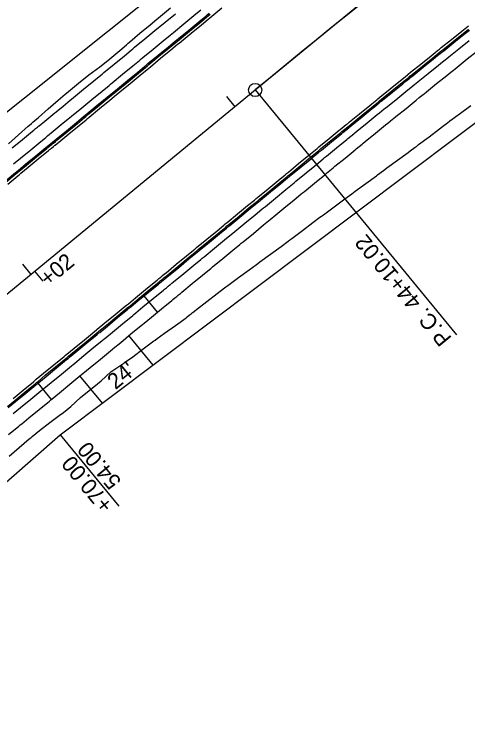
# Model space of a CAD drawing. Extents: x 1147550 to 1149124, y 2017436 to 2018779.
# Drawn here: x 1147734.3 to 1147906, y 2017436.4 to 2017707.7 of the extents above; entities that cross this region are included whole.
import ezdxf

# ---------------------------------------------------------------- set-up
doc = ezdxf.new("R2010")
doc.units = 0
for name, color, linetype in [('S_EDGE_CONCRETE', 7, 'Continuous'), ('S_ELECTRIC_UTILITIES', 7, 'Continuous'), ('S_HEADWALL', 7, 'Continuous'), ('S_MAILBOX', 7, 'Continuous'), ('S_RDW_PT_SYM', 7, 'Continuous'), ('S_SECONDARY_CTL', 7, 'Continuous'), ('S_TELEPHONE_UTILITIES', 7, 'Continuous')]:
    doc.layers.add(name, color=color, linetype=linetype)

msp = doc.modelspace()

# ---------------------------------------------------------------- linework, layer by layer
at = {"layer": 'S_EDGE_CONCRETE'}
for p, q in [((1147825.51, 2017679.08), (1148011.14, 2017831.73)), ((1147586.06, 2017482.16), (1147825.51, 2017679.08))]:
    msp.add_line(p, q, dxfattribs=at)
for points in [[(1147814.6, 2017676.58), (1147817.77, 2017672.72)], [(1147737.36, 2017613.06), (1147740.54, 2017609.2)]]:
    msp.add_lwpolyline(points, dxfattribs=at)
msp.add_circle((1147825.51, 2017679.08), 2.5, dxfattribs=at)
msp.add_arc((1151464.82, 2013253.76), 5729.58, 124.62946, 129.43332, dxfattribs=at)
at = {"layer": 'S_ELECTRIC_UTILITIES'}
msp.add_lwpolyline([(1147751.67, 2017548.43), (1147773.9, 2017521.4)], dxfattribs=at)
at = {"layer": 'S_HEADWALL'}
for p, q in [((1147745.26, 2017606.61), (1147742.08, 2017610.47)), ((1147788.52, 2017594.93), (1147783.44, 2017601.11)), ((1147786.87, 2017574.91), (1147777.71, 2017586.04)), ((1147767.67, 2017560.47), (1147759.17, 2017570.79)), ((1147748.36, 2017561.9), (1147743.28, 2017568.08))]:
    msp.add_line(p, q, dxfattribs=at)
at = {"layer": 'S_MAILBOX'}
for points in [[(1147550.1, 2017525.89), (1147894.72, 2017801.4), (1147903.55, 2017831.14), (1148035.64, 2017933.4), (1148261.5, 2018084.85), (1148285.74, 2018084.65), (1148479.1, 2018223.18), (1148835.76, 2018573.62)], [(1147623.68, 2017436.42), (1147751.67, 2017548.43), (1147958.55, 2017704.02), (1148020.45, 2017753.36), (1148124.6, 2017828.73), (1148174.25, 2017853.51), (1148282.74, 2017941.53), (1148421.63, 2018031.39), (1148612.18, 2018197.22), (1148639.91, 2018214.06), (1148753.45, 2018306.48), (1148799.03, 2018350.69)]]:
    msp.add_lwpolyline(points, dxfattribs=at)
at = {"layer": 'S_RDW_PT_SYM'}
msp.add_lwpolyline([(1147825.51, 2017679.08), (1147901.73, 2017586.39)], dxfattribs=at)
at = {"layer": 'S_SECONDARY_CTL'}
for points in [[(1147732.17, 2017658.73), (1147735.88, 2017662.1), (1147739.61, 2017665.43), (1147740.04, 2017665.8), (1147740.76, 2017666.41), (1147741.44, 2017666.99), (1147742, 2017667.46), (1147742.1, 2017667.55), (1147742.83, 2017668.16), (1147743.42, 2017668.66), (1147747.18, 2017671.97), (1147750.95, 2017675.26), (1147753.57, 2017677.45), (1147754.06, 2017677.87), (1147754.78, 2017678.47), (1147758.61, 2017681.68), (1147762.55, 2017684.76), (1147765.28, 2017686.81), (1147765.8, 2017687.2), (1147766.55, 2017687.77), (1147770.47, 2017690.88), (1147774.31, 2017694.08), (1147776.82, 2017696.23), (1147777.46, 2017696.78), (1147778.11, 2017697.34), (1147781.89, 2017700.6), (1147785.74, 2017703.79), (1147788.32, 2017705.92), (1147788.9, 2017706.4), (1147789.6, 2017706.98), (1147793.45, 2017710.16)], [(1147732.37, 2017540.41), (1147736.17, 2017543.66), (1147739.97, 2017546.91), (1147740.53, 2017547.38), (1147741.05, 2017547.83), (1147743.83, 2017550.09), (1147747.82, 2017553.12), (1147751.8, 2017556.14), (1147752.39, 2017556.58), (1147752.93, 2017556.99), (1147755.72, 2017559.25), (1147759.42, 2017562.63), (1147763.3, 2017565.77), (1147763.87, 2017566.23), (1147764.4, 2017566.66), (1147767.19, 2017568.91), (1147770.91, 2017572.27), (1147775.01, 2017575.16), (1147775.74, 2017575.65), (1147776.04, 2017575.87), (1147779.15, 2017577.99), (1147783.07, 2017581.09), (1147787.13, 2017584.03), (1147787.6, 2017584.36), (1147788.37, 2017584.92), (1147791.2, 2017586.96), (1147795.28, 2017589.87), (1147799.32, 2017592.83), (1147799.77, 2017593.18), (1147800.51, 2017593.76), (1147801.22, 2017594.3), (1147801.8, 2017594.75), (1147801.9, 2017594.83), (1147802.65, 2017595.41), (1147803.27, 2017595.89), (1147807.22, 2017598.96), (1147811.17, 2017602.03), (1147813.87, 2017604.12), (1147814.39, 2017604.52), (1147815.12, 2017605.09), (1147819.15, 2017608.07), (1147823.2, 2017611.01), (1147825.97, 2017613.02), (1147826.5, 2017613.4), (1147827.26, 2017613.95), (1147831.31, 2017616.89), (1147835.37, 2017619.83), (1147838.01, 2017621.82), (1147838.69, 2017622.34), (1147839.36, 2017622.85), (1147843.37, 2017625.85), (1147847.38, 2017628.85), (1147850.05, 2017630.85), (1147850.67, 2017631.3), (1147851.39, 2017631.84), (1147855.4, 2017634.83), (1147859.43, 2017637.8), (1147859.45, 2017637.81), (1147862.09, 2017639.77), (1147862.69, 2017640.21), (1147863.42, 2017640.75), (1147867.42, 2017643.69), (1147871.42, 2017646.62), (1147871.83, 2017646.92), (1147874.13, 2017648.62), (1147874.59, 2017648.95), (1147875.42, 2017649.56), (1147879.42, 2017652.48), (1147883.41, 2017655.42), (1147884.22, 2017656.02), (1147886.13, 2017657.43), (1147886.54, 2017657.74), (1147887.39, 2017658.39), (1147891.33, 2017661.39), (1147895.27, 2017664.38), (1147896.46, 2017665.28), (1147897.97, 2017666.43), (1147898.34, 2017666.7), (1147899.22, 2017667.37), (1147903.21, 2017670.32), (1147907.2, 2017673.25)]]:
    msp.add_lwpolyline(points, dxfattribs=at)
at = {"layer": 'S_TELEPHONE_UTILITIES'}
for points in [[(1147731.8, 2017643.44), (1147735.66, 2017646.62), (1147736.1, 2017646.98), (1147736.83, 2017647.58), (1147739.52, 2017649.79), (1147743.38, 2017652.97), (1147747.24, 2017656.14), (1147747.68, 2017656.51), (1147748.41, 2017657.11), (1147749.1, 2017657.67), (1147749.67, 2017658.14), (1147749.77, 2017658.22), (1147750.5, 2017658.82), (1147751.11, 2017659.32), (1147754.97, 2017662.5), (1147758.83, 2017665.67), (1147761.47, 2017667.84), (1147761.97, 2017668.26), (1147762.69, 2017668.85), (1147766.55, 2017672.02), (1147770.42, 2017675.2), (1147773.05, 2017677.37), (1147773.55, 2017677.78), (1147774.28, 2017678.38), (1147778.14, 2017681.55), (1147782, 2017684.73), (1147784.55, 2017686.82), (1147785.21, 2017687.36), (1147785.86, 2017687.9), (1147789.72, 2017691.08), (1147793.59, 2017694.26), (1147796.16, 2017696.38), (1147796.75, 2017696.86), (1147797.45, 2017697.43), (1147801.31, 2017700.61), (1147805.17, 2017703.78), (1147805.18, 2017703.79), (1147807.76, 2017705.91), (1147808.34, 2017706.39), (1147809.06, 2017706.98), (1147812.94, 2017710.16)], [(1147730.84, 2017644.6), (1147734.71, 2017647.78), (1147735.15, 2017648.14), (1147735.88, 2017648.74), (1147738.57, 2017650.95), (1147742.43, 2017654.13), (1147746.29, 2017657.3), (1147746.73, 2017657.67), (1147747.46, 2017658.27), (1147748.15, 2017658.83), (1147748.72, 2017659.3), (1147748.82, 2017659.38), (1147749.55, 2017659.98), (1147750.15, 2017660.48), (1147754.02, 2017663.66), (1147757.88, 2017666.83), (1147760.52, 2017669), (1147761.02, 2017669.41), (1147761.74, 2017670.01), (1147765.6, 2017673.18), (1147769.46, 2017676.36), (1147772.1, 2017678.53), (1147772.6, 2017678.94), (1147773.32, 2017679.53), (1147777.19, 2017682.71), (1147781.05, 2017685.89), (1147783.6, 2017687.98), (1147784.25, 2017688.52), (1147784.91, 2017689.06), (1147788.77, 2017692.24), (1147792.63, 2017695.41), (1147795.21, 2017697.53), (1147795.8, 2017698.02), (1147796.5, 2017698.59), (1147800.36, 2017701.77), (1147804.22, 2017704.94), (1147804.23, 2017704.95), (1147806.81, 2017707.07), (1147807.39, 2017707.55), (1147808.1, 2017708.13)], [(1147731.16, 2017644.21), (1147735.02, 2017647.39), (1147735.47, 2017647.76), (1147736.2, 2017648.36), (1147738.89, 2017650.57), (1147742.75, 2017653.74), (1147746.61, 2017656.92), (1147747.05, 2017657.28), (1147747.78, 2017657.88), (1147748.47, 2017658.45), (1147749.04, 2017658.91), (1147749.14, 2017659), (1147749.87, 2017659.6), (1147750.47, 2017660.09), (1147754.33, 2017663.27), (1147758.19, 2017666.44), (1147760.84, 2017668.62), (1147761.34, 2017669.03), (1147762.06, 2017669.62), (1147765.92, 2017672.8), (1147769.78, 2017675.97), (1147772.41, 2017678.14), (1147772.92, 2017678.55), (1147773.64, 2017679.15), (1147777.5, 2017682.32), (1147781.37, 2017685.5), (1147783.92, 2017687.6), (1147784.57, 2017688.14), (1147785.23, 2017688.68), (1147789.09, 2017691.85), (1147792.95, 2017695.03), (1147795.53, 2017697.15), (1147796.12, 2017697.63), (1147796.81, 2017698.2), (1147800.67, 2017701.38), (1147804.54, 2017704.56), (1147804.55, 2017704.57), (1147807.13, 2017706.68), (1147807.71, 2017707.16), (1147808.42, 2017707.75)], [(1147733.49, 2017657.13), (1147737.35, 2017660.31), (1147741.21, 2017663.48), (1147741.65, 2017663.84), (1147742.38, 2017664.44), (1147743.07, 2017665.01), (1147743.64, 2017665.48), (1147743.74, 2017665.56), (1147744.47, 2017666.16), (1147745.07, 2017666.66), (1147748.93, 2017669.83), (1147752.8, 2017673.01), (1147755.44, 2017675.18), (1147755.94, 2017675.59), (1147756.66, 2017676.19), (1147760.52, 2017679.36), (1147764.38, 2017682.54), (1147767.02, 2017684.7), (1147767.52, 2017685.12), (1147768.24, 2017685.71), (1147772.1, 2017688.89), (1147775.97, 2017692.07), (1147778.52, 2017694.16), (1147779.17, 2017694.7), (1147779.83, 2017695.24), (1147783.69, 2017698.42), (1147787.55, 2017701.59), (1147790.13, 2017703.71), (1147790.72, 2017704.2), (1147791.41, 2017704.77), (1147795.28, 2017707.94)], [(1147733.98, 2017651.06), (1147736.66, 2017653.27), (1147740.52, 2017656.44), (1147744.39, 2017659.62), (1147744.83, 2017659.98), (1147745.56, 2017660.58), (1147746.25, 2017661.15), (1147746.81, 2017661.62), (1147746.92, 2017661.7), (1147747.64, 2017662.3), (1147748.25, 2017662.8), (1147752.11, 2017665.97), (1147755.97, 2017669.15), (1147758.61, 2017671.32), (1147759.11, 2017671.73), (1147759.83, 2017672.32), (1147763.7, 2017675.5), (1147767.56, 2017678.68), (1147770.19, 2017680.84), (1147770.69, 2017681.25), (1147771.42, 2017681.85), (1147775.28, 2017685.03), (1147779.14, 2017688.2), (1147781.69, 2017690.3), (1147782.35, 2017690.84), (1147783, 2017691.38), (1147786.87, 2017694.56), (1147790.73, 2017697.73), (1147793.31, 2017699.85), (1147793.89, 2017700.34), (1147794.59, 2017700.91), (1147798.45, 2017704.08), (1147802.31, 2017707.26), (1147802.33, 2017707.27), (1147804.9, 2017709.39)], [(1147731.7, 2017559.21), (1147734.47, 2017561.48), (1147738.33, 2017564.65), (1147742.19, 2017567.83), (1147742.76, 2017568.3), (1147743.28, 2017568.73), (1147746.05, 2017571.01), (1147749.91, 2017574.18), (1147753.77, 2017577.36), (1147754.34, 2017577.82), (1147754.86, 2017578.25), (1147757.64, 2017580.53), (1147761.5, 2017583.71), (1147765.36, 2017586.89), (1147766.04, 2017587.45), (1147766.33, 2017587.68), (1147769.22, 2017590.06), (1147773.08, 2017593.24), (1147776.95, 2017596.41), (1147777.39, 2017596.78), (1147778.12, 2017597.38), (1147780.81, 2017599.59), (1147784.67, 2017602.77), (1147788.53, 2017605.94), (1147788.97, 2017606.3), (1147789.7, 2017606.9), (1147790.39, 2017607.47), (1147790.96, 2017607.94), (1147791.06, 2017608.02), (1147791.79, 2017608.62), (1147792.39, 2017609.12), (1147796.25, 2017612.29), (1147800.12, 2017615.47), (1147802.76, 2017617.64), (1147803.26, 2017618.05), (1147803.98, 2017618.64), (1147807.84, 2017621.82), (1147811.7, 2017625), (1147814.34, 2017627.16), (1147814.84, 2017627.57), (1147815.56, 2017628.17), (1147819.43, 2017631.35), (1147823.29, 2017634.52), (1147825.84, 2017636.62), (1147826.49, 2017637.16), (1147827.15, 2017637.7), (1147831.01, 2017640.88), (1147834.87, 2017644.05), (1147837.45, 2017646.17), (1147838.04, 2017646.66), (1147838.73, 2017647.23), (1147842.6, 2017650.4), (1147846.46, 2017653.58), (1147846.47, 2017653.59), (1147849.02, 2017655.68), (1147849.59, 2017656.15), (1147850.3, 2017656.74), (1147854.14, 2017659.89), (1147857.99, 2017663.04), (1147858.38, 2017663.36), (1147860.6, 2017665.17), (1147861.05, 2017665.54), (1147861.84, 2017666.18), (1147865.69, 2017669.33), (1147869.55, 2017672.47), (1147870.32, 2017673.1), (1147872.17, 2017674.6), (1147872.57, 2017674.93), (1147873.4, 2017675.6), (1147877.26, 2017678.73), (1147881.13, 2017681.86), (1147882.29, 2017682.8), (1147883.77, 2017684), (1147884.12, 2017684.29), (1147884.99, 2017684.99), (1147888.86, 2017688.11), (1147892.73, 2017691.23), (1147894.28, 2017692.48), (1147895.22, 2017693.23), (1147895.86, 2017693.75), (1147896.6, 2017694.34), (1147900.48, 2017697.46), (1147904.36, 2017700.57), (1147906.3, 2017702.12)], [(1147733.83, 2017562.25), (1147737.69, 2017565.43), (1147741.55, 2017568.6), (1147742.12, 2017569.07), (1147742.64, 2017569.5), (1147745.42, 2017571.78), (1147749.28, 2017574.95), (1147753.14, 2017578.13), (1147753.71, 2017578.6), (1147754.23, 2017579.02), (1147757, 2017581.31), (1147760.86, 2017584.48), (1147764.73, 2017587.66), (1147765.41, 2017588.22), (1147765.69, 2017588.45), (1147768.59, 2017590.83), (1147772.45, 2017594.01), (1147776.31, 2017597.19), (1147776.76, 2017597.55), (1147777.49, 2017598.15), (1147780.17, 2017600.36), (1147784.03, 2017603.54), (1147787.9, 2017606.71), (1147788.34, 2017607.08), (1147789.07, 2017607.68), (1147789.76, 2017608.24), (1147790.32, 2017608.71), (1147790.42, 2017608.79), (1147791.15, 2017609.39), (1147791.76, 2017609.89), (1147795.62, 2017613.07), (1147799.48, 2017616.24), (1147802.12, 2017618.41), (1147802.62, 2017618.82), (1147803.34, 2017619.42), (1147807.21, 2017622.59), (1147811.07, 2017625.77), (1147813.7, 2017627.94), (1147814.2, 2017628.35), (1147814.93, 2017628.94), (1147818.79, 2017632.12), (1147822.65, 2017635.3), (1147825.2, 2017637.39), (1147825.86, 2017637.93), (1147826.51, 2017638.47), (1147830.38, 2017641.65), (1147834.24, 2017644.82), (1147836.82, 2017646.94), (1147837.4, 2017647.43), (1147838.1, 2017648), (1147841.96, 2017651.18), (1147845.82, 2017654.35), (1147845.84, 2017654.36), (1147848.38, 2017656.46), (1147848.96, 2017656.93), (1147849.67, 2017657.51), (1147853.51, 2017660.66), (1147857.36, 2017663.81), (1147857.75, 2017664.13), (1147859.97, 2017665.95), (1147860.42, 2017666.31), (1147861.21, 2017666.96), (1147865.06, 2017670.1), (1147868.91, 2017673.24), (1147869.69, 2017673.87), (1147871.54, 2017675.38), (1147871.94, 2017675.7), (1147872.77, 2017676.38), (1147876.63, 2017679.51), (1147880.5, 2017682.64), (1147881.66, 2017683.58), (1147883.14, 2017684.78), (1147883.5, 2017685.06), (1147884.36, 2017685.77), (1147888.23, 2017688.89), (1147892.1, 2017692.01), (1147893.65, 2017693.26), (1147894.59, 2017694.01), (1147895.24, 2017694.53), (1147895.98, 2017695.12), (1147899.86, 2017698.24), (1147903.74, 2017701.35), (1147905.67, 2017702.9), (1147906.24, 2017703.35)], [(1147732.02, 2017558.82), (1147734.78, 2017561.09), (1147738.65, 2017564.27), (1147742.51, 2017567.44), (1147743.08, 2017567.91), (1147743.6, 2017568.34), (1147746.37, 2017570.62), (1147750.23, 2017573.8), (1147754.09, 2017576.97), (1147754.66, 2017577.44), (1147755.18, 2017577.87), (1147757.95, 2017580.15), (1147761.82, 2017583.32), (1147765.68, 2017586.5), (1147766.36, 2017587.06), (1147766.65, 2017587.29), (1147769.54, 2017589.68), (1147773.4, 2017592.85), (1147777.26, 2017596.03), (1147777.71, 2017596.39), (1147778.44, 2017596.99), (1147781.13, 2017599.2), (1147784.99, 2017602.38), (1147788.85, 2017605.55), (1147789.29, 2017605.92), (1147790.02, 2017606.52), (1147790.71, 2017607.08), (1147791.28, 2017607.55), (1147791.38, 2017607.63), (1147792.11, 2017608.23), (1147792.71, 2017608.73), (1147796.57, 2017611.91), (1147800.43, 2017615.08), (1147803.07, 2017617.25), (1147803.57, 2017617.67), (1147804.3, 2017618.26), (1147808.16, 2017621.43), (1147812.02, 2017624.61), (1147814.65, 2017626.78), (1147815.15, 2017627.19), (1147815.88, 2017627.79), (1147819.74, 2017630.96), (1147823.61, 2017634.14), (1147826.16, 2017636.24), (1147826.81, 2017636.77), (1147827.47, 2017637.31), (1147831.33, 2017640.49), (1147835.19, 2017643.67), (1147837.77, 2017645.79), (1147838.36, 2017646.27), (1147839.05, 2017646.84), (1147842.91, 2017650.02), (1147846.78, 2017653.19), (1147846.79, 2017653.2), (1147849.33, 2017655.3), (1147849.91, 2017655.77), (1147850.62, 2017656.35), (1147854.46, 2017659.5), (1147858.31, 2017662.65), (1147858.7, 2017662.97), (1147860.92, 2017664.79), (1147861.36, 2017665.15), (1147862.16, 2017665.8), (1147866.01, 2017668.94), (1147869.86, 2017672.08), (1147870.64, 2017672.71), (1147872.49, 2017674.21), (1147872.89, 2017674.54), (1147873.72, 2017675.21), (1147877.58, 2017678.34), (1147881.44, 2017681.47), (1147882.6, 2017682.41), (1147884.08, 2017683.61), (1147884.44, 2017683.9), (1147885.31, 2017684.6), (1147889.17, 2017687.72), (1147893.04, 2017690.84), (1147894.59, 2017692.09), (1147895.53, 2017692.84), (1147896.18, 2017693.36), (1147896.92, 2017693.95), (1147900.79, 2017697.07), (1147904.67, 2017700.18), (1147906.61, 2017701.73)], [(1147733.92, 2017556.5), (1147736.69, 2017558.78), (1147740.55, 2017561.95), (1147744.41, 2017565.13), (1147744.98, 2017565.6), (1147745.5, 2017566.02), (1147748.27, 2017568.3), (1147752.14, 2017571.48), (1147756, 2017574.65), (1147756.56, 2017575.12), (1147757.08, 2017575.55), (1147759.86, 2017577.83), (1147763.72, 2017581.01), (1147767.58, 2017584.18), (1147768.26, 2017584.74), (1147768.55, 2017584.98), (1147771.45, 2017587.36), (1147775.31, 2017590.53), (1147779.17, 2017593.71), (1147779.61, 2017594.08), (1147780.34, 2017594.68), (1147783.03, 2017596.89), (1147786.89, 2017600.06), (1147790.75, 2017603.24), (1147791.19, 2017603.6), (1147791.92, 2017604.2), (1147792.61, 2017604.77), (1147793.18, 2017605.23), (1147793.28, 2017605.32), (1147794.01, 2017605.92), (1147794.62, 2017606.41), (1147798.48, 2017609.59), (1147802.34, 2017612.77), (1147804.98, 2017614.94), (1147805.48, 2017615.35), (1147806.2, 2017615.94), (1147810.06, 2017619.12), (1147813.93, 2017622.29), (1147816.56, 2017624.46), (1147817.06, 2017624.87), (1147817.79, 2017625.47), (1147821.65, 2017628.65), (1147825.51, 2017631.82), (1147828.06, 2017633.92), (1147828.72, 2017634.46), (1147829.37, 2017635), (1147833.23, 2017638.17), (1147837.1, 2017641.35), (1147839.67, 2017643.47), (1147840.26, 2017643.95), (1147840.96, 2017644.52), (1147844.82, 2017647.7), (1147848.68, 2017650.88), (1147848.69, 2017650.89), (1147851.24, 2017652.98), (1147851.81, 2017653.45), (1147852.52, 2017654.03), (1147856.36, 2017657.18), (1147860.21, 2017660.33), (1147860.6, 2017660.65), (1147862.82, 2017662.46), (1147863.26, 2017662.83), (1147864.05, 2017663.47), (1147867.9, 2017666.61), (1147871.75, 2017669.75), (1147872.53, 2017670.38), (1147874.38, 2017671.89), (1147874.78, 2017672.21), (1147875.61, 2017672.88), (1147879.47, 2017676.01), (1147883.33, 2017679.14), (1147884.49, 2017680.08), (1147885.97, 2017681.28), (1147886.32, 2017681.56), (1147887.19, 2017682.27), (1147891.06, 2017685.39), (1147894.93, 2017688.5), (1147896.47, 2017689.75), (1147897.41, 2017690.5), (1147898.06, 2017691.02), (1147898.8, 2017691.62), (1147902.67, 2017694.73), (1147906.55, 2017697.83)], [(1147732.14, 2017548.56), (1147736, 2017551.74), (1147736.57, 2017552.2), (1147737.1, 2017552.64), (1147739.86, 2017554.91), (1147743.73, 2017558.09), (1147747.59, 2017561.27), (1147748.16, 2017561.73), (1147748.68, 2017562.16), (1147751.45, 2017564.44), (1147755.31, 2017567.62), (1147759.17, 2017570.79), (1147759.74, 2017571.26), (1147760.26, 2017571.69), (1147763.04, 2017573.97), (1147766.9, 2017577.14), (1147770.76, 2017580.32), (1147771.44, 2017580.88), (1147771.73, 2017581.12), (1147774.62, 2017583.5), (1147778.48, 2017586.67), (1147782.34, 2017589.85), (1147782.79, 2017590.21), (1147783.52, 2017590.81), (1147786.21, 2017593.02), (1147790.07, 2017596.2), (1147793.93, 2017599.38), (1147794.37, 2017599.74), (1147795.1, 2017600.34), (1147795.79, 2017600.91), (1147796.36, 2017601.37), (1147796.46, 2017601.46), (1147797.19, 2017602.06), (1147797.79, 2017602.55), (1147801.65, 2017605.73), (1147805.52, 2017608.9), (1147808.16, 2017611.08), (1147808.66, 2017611.49), (1147809.38, 2017612.08), (1147813.24, 2017615.26), (1147817.1, 2017618.43), (1147819.74, 2017620.6), (1147820.24, 2017621.01), (1147820.96, 2017621.61), (1147824.82, 2017624.78), (1147828.69, 2017627.96), (1147831.24, 2017630.06), (1147831.89, 2017630.6), (1147832.55, 2017631.14), (1147836.41, 2017634.31), (1147840.27, 2017637.49), (1147842.85, 2017639.61), (1147843.44, 2017640.09), (1147844.13, 2017640.66), (1147848, 2017643.84), (1147851.86, 2017647.01), (1147851.87, 2017647.02), (1147854.41, 2017649.11), (1147854.99, 2017649.59), (1147855.69, 2017650.17), (1147859.53, 2017653.31), (1147863.37, 2017656.46), (1147863.77, 2017656.78), (1147865.98, 2017658.59), (1147866.43, 2017658.95), (1147867.21, 2017659.6), (1147871.06, 2017662.74), (1147874.91, 2017665.87), (1147875.69, 2017666.5), (1147877.53, 2017668), (1147877.93, 2017668.33), (1147878.76, 2017669), (1147882.62, 2017672.13), (1147886.47, 2017675.25), (1147887.63, 2017676.19), (1147889.11, 2017677.39), (1147889.47, 2017677.68), (1147890.33, 2017678.38), (1147894.2, 2017681.49), (1147898.06, 2017684.61), (1147899.61, 2017685.85), (1147900.55, 2017686.61), (1147901.19, 2017687.12), (1147901.93, 2017687.72), (1147905.8, 2017690.83), (1147909.67, 2017693.93)]]:
    msp.add_lwpolyline(points, dxfattribs=at)

# ---------------------------------------------------------------- texts
at = {"layer": 'S_ELECTRIC_UTILITIES'}
for s, p in [('54.00', (1147775.12, 2017530.94)), ('+70.00', (1147772.11, 2017522))]:
    msp.add_text(s, height=6, rotation=129.4333, dxfattribs=at).set_placement(p)
at = {"layer": 'S_HEADWALL'}
for s, p in [('+02', (1147747.04, 2017604.44)), ("24'", (1147772.63, 2017565.37))]:
    msp.add_text(s, height=6, rotation=39.4333, dxfattribs=at).set_placement(p)
at = {"layer": 'S_RDW_PT_SYM'}
msp.add_text('P.C. 44+10.02', height=6, rotation=129.4333, dxfattribs=at).set_placement((1147900.19, 2017585.12))

doc.saveas('drawing.dxf')
